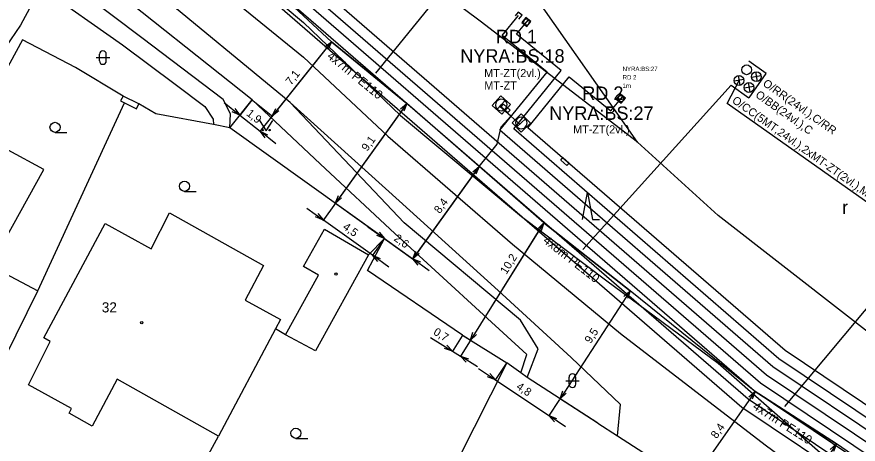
# Model space of a CAD drawing. Extents: x -836739 to -834468, y -1071001 to -1070126.
# Drawn here: x -836501 to -836438.6, y -1070362.4 to -1070330.7 of the extents above; entities that cross this region are included whole.
import ezdxf

# ---------------------------------------------------------------- set-up
doc = ezdxf.new("R2010")
doc.units = 0
for name, color, linetype in [('f001_pol_linie', 7, 'Continuous'), ('f001_pol_texty', 7, 'Continuous'), ('f001_pol_znacky', 7, 'Continuous'), ('f002_inz_linie_mimo_CETIN', 7, 'Continuous'), ('f003_opt_sit_texty', 7, 'Continuous'), ('f003_opt_sit_znacky', 7, 'Continuous'), ('f006_osa_trasy', 7, 'Continuous'), ('f006_stp_koty', 7, 'Continuous'), ('f006_stp_linie', 7, 'Continuous'), ('f006_stp_texty', 7, 'Continuous'), ('f007_rezkynet_linie', 7, 'Continuous'), ('f007_rezkynet_texty', 7, 'Continuous'), ('f007_rezkynet_znacky', 7, 'Continuous'), ('f309_rozvadec_opt', 7, 'Continuous'), ('f309_rozvadec_opt_ann', 7, 'Continuous'), ('f309_trub_konc_zar', 7, 'Continuous'), ('f309_trubicka', 7, 'Continuous'), ('f309_trubka', 7, 'Continuous')]:
    doc.layers.add(name, color=color, linetype=linetype)

msp = doc.modelspace()

# ---------------------------------------------------------------- linework, layer by layer
at = {"layer": 'f001_pol_linie'}
for points in [[(-836356.62, -1070406.87), (-836370.19, -1070399.44), (-836385.43, -1070392.2), (-836396.38, -1070386.03), (-836404.41, -1070381.11), (-836409.87, -1070376.61), (-836425.28, -1070363.93), (-836449.03, -1070345.44), (-836455, -1070340), (-836462.64, -1070329.11), (-836464.81, -1070325.47), (-836465.74, -1070321.03), (-836464.89, -1070314.87), (-836461.62, -1070306.74), (-836456.41, -1070297.54), (-836450.95, -1070288.2), (-836447.03, -1070272.79), (-836441.38, -1070260.76)], [(-836496.52, -1070319.54), (-836488.05, -1070326.94), (-836479.74, -1070333.71), (-836473.51, -1070339.57), (-836464.27, -1070347.56), (-836456.25, -1070354.2), (-836445.54, -1070362.45), (-836432.86, -1070371.82), (-836421.65, -1070379.55), (-836415.3, -1070382.95)], [(-836490.91, -1070321.78), (-836479.74, -1070331.15), (-836472.55, -1070338.03), (-836463.6, -1070345.51), (-836457.27, -1070350.28), (-836449.01, -1070356.39), (-836440.87, -1070363.54), (-836429.17, -1070372.36), (-836419.16, -1070378.17), (-836410.31, -1070384.67), (-836403.72, -1070387.61), (-836401.28, -1070388.23), (-836398.49, -1070390.5), (-836396.2, -1070392.51)], [(-836456.49, -1070361.78), (-836456.25, -1070359.46), (-836459.92, -1070355.96), (-836465.33, -1070351.01), (-836472.65, -1070344.35), (-836480.74, -1070337.07), (-836490.99, -1070328.59), (-836496.17, -1070324.43), (-836496.72, -1070324.41), (-836497.13, -1070324.67), (-836498.53, -1070327.13), (-836499.22, -1070328.53), (-836500.71, -1070331.34), (-836502.21, -1070333.5), (-836505.09, -1070337.45), (-836506.09, -1070338.88), (-836509.04, -1070344.01), (-836513.54, -1070341.59), (-836515.98, -1070341.87)], [(-836455, -1070340), (-836466.66, -1070331.05), (-836473.91, -1070325.6), (-836480.18, -1070324.33)], [(-836485.21, -1070338.94), (-836485.15, -1070337.91), (-836485.7, -1070336.85), (-836491.73, -1070332.27), (-836498.53, -1070327.13)], [(-836485.21, -1070338.94), (-836483.56, -1070336.88), (-836494.94, -1070327.8)], [(-836499.22, -1070328.53), (-836493.15, -1070332.79), (-836489.26, -1070335.71), (-836487.05, -1070337.37), (-836486.43, -1070338.3), (-836486.41, -1070338.71)], [(-836493.1, -1070336.59), (-836496.65, -1070334.47), (-836500.57, -1070332.42), (-836503.41, -1070337.61)], [(-836491.94, -1070337.17), (-836493.1, -1070336.59), (-836493.3, -1070336.95), (-836493.01, -1070337.1), (-836492.13, -1070337.55), (-836491.94, -1070337.17)], [(-836502.34, -1070355.64), (-836501.82, -1070355.9), (-836499.44, -1070351.03), (-836494.05, -1070339.35), (-836493.01, -1070337.1)], [(-836490.7, -1070337.9), (-836491.94, -1070337.17)], [(-836463.65, -1070357.11), (-836463.2, -1070355.75), (-836466.41, -1070352.81), (-836472.98, -1070346.78), (-836478.5, -1070341.63), (-836483.56, -1070336.88)], [(-836463.18, -1070357.45), (-836462.35, -1070355.33), (-836463.68, -1070353.2), (-836472.3, -1070346), (-836480.74, -1070337.07)], [(-836485.21, -1070338.94), (-836486.41, -1070338.71), (-836490.7, -1070337.9)], [(-836502.49, -1070348.34), (-836498.99, -1070342.03), (-836504.3, -1070339.18)], [(-836467.97, -1070354.32), (-836475.01, -1070349.53), (-836473.75, -1070347.16), (-836485.21, -1070338.94)], [(-836486.05, -1070361.8), (-836493.56, -1070357.58), (-836495.41, -1070361.07), (-836497.11, -1070360.09), (-836496.94, -1070359.76), (-836500.13, -1070357.99), (-836498.52, -1070354.78), (-836498.99, -1070354.52), (-836494.45, -1070346.05), (-836491.04, -1070347.91), (-836489.68, -1070345.25), (-836482.72, -1070349.16), (-836484.08, -1070351.72), (-836481.46, -1070353.16), (-836481.83, -1070353.85), (-836486.05, -1070361.8)], [(-836508.36, -1070346.32), (-836499.44, -1070351.03)], [(-836478.19, -1070346.45), (-836474.93, -1070348.36), (-836478.86, -1070355.48), (-836481.08, -1070354.28), (-836478.63, -1070349.88), (-836479.76, -1070349.22), (-836478.19, -1070346.45)], [(-836474.93, -1070348.36), (-836473.75, -1070347.16)], [(-836481.08, -1070354.28), (-836481.83, -1070353.85)], [(-836467.97, -1070354.32), (-836464.69, -1070356.37)], [(-836467.97, -1070354.32), (-836464.69, -1070356.37)], [(-836464.69, -1070356.37), (-836475.54, -1070377.9)], [(-836457.94, -1070360.84), (-836463.18, -1070357.45), (-836463.65, -1070357.11), (-836464.69, -1070356.37)], [(-836457.94, -1070360.84), (-836456.49, -1070361.78)], [(-836457.94, -1070360.84), (-836456.49, -1070361.78)], [(-836490.64, -1070370.23), (-836486.05, -1070361.8)], [(-836456.49, -1070361.78), (-836452.99, -1070364.02)]]:
    msp.add_lwpolyline(points, dxfattribs=at)
at = {"layer": 'f001_pol_znacky'}
for p, q in [((-836494.86, -1070333.99), (-836494.86, -1070333.49)), ((-836494.36, -1070333.99), (-836494.36, -1070333.49)), ((-836495.11, -1070333.74), (-836494.11, -1070333.74)), ((-836498.16, -1070339.285), (-836497.285, -1070339.285)), ((-836488.57, -1070343.655), (-836487.695, -1070343.655)), ((-836460.32, -1070357.69), (-836459.32, -1070357.69)), ((-836460.07, -1070357.94), (-836460.07, -1070357.44)), ((-836459.57, -1070357.94), (-836459.57, -1070357.44)), ((-836480.31, -1070361.965), (-836479.435, -1070361.965))]:
    msp.add_line(p, q, dxfattribs=at)
for points in [[(-836483.01, -1070338.41), (-836482.51, -1070339.16), (-836482.01, -1070338.41)], [(-836459.075, -1070345.75), (-836458.7, -1070343.75), (-836458.325, -1070345.75), (-836457.825, -1070345.75)]]:
    msp.add_lwpolyline(points, dxfattribs=at)
for centre, radius in [((-836498.16, -1070338.91), 0.375), ((-836482.76, -1070339.11), 0.05), ((-836482.26, -1070339.11), 0.05), ((-836488.57, -1070343.28), 0.375), ((-836477.34, -1070349.79), 0.0875), ((-836491.73, -1070353.4), 0.0875), ((-836480.31, -1070361.59), 0.375)]:
    msp.add_circle(centre, radius, dxfattribs=at)
for centre, start, end in [((-836494.61, -1070333.49), 0, 179.99999), ((-836494.61, -1070333.99), 179.99999, 359.99999), ((-836459.82, -1070357.44), 0, 179.99999), ((-836459.82, -1070357.94), 179.99999, 359.99999)]:
    msp.add_arc(centre, 0.25, start, end, dxfattribs=at)
at = {"layer": 'f002_inz_linie_mimo_CETIN'}
for points in [[(-836465.09, -1070337.39), (-836464.93, -1070337.2), (-836464.44, -1070337.63), (-836464.61, -1070337.82)], [(-836465.09, -1070337.39), (-836464.93, -1070337.2), (-836464.44, -1070337.63), (-836464.61, -1070337.82)], [(-836465.09, -1070337.39), (-836464.61, -1070337.82)], [(-836465.09, -1070337.39), (-836464.61, -1070337.82)], [(-836460.69, -1070341.34), (-836460.53, -1070341.15), (-836460.07, -1070341.56), (-836460.23, -1070341.75)], [(-836460.69, -1070341.34), (-836460.53, -1070341.15), (-836460.07, -1070341.56), (-836460.23, -1070341.75)], [(-836460.69, -1070341.34), (-836460.23, -1070341.75)], [(-836460.69, -1070341.34), (-836460.23, -1070341.75)]]:
    msp.add_lwpolyline(points, dxfattribs=at)
at = {"layer": 'f003_opt_sit_znacky'}
for p, q in [((-836464.81, -1070336.929), (-836465.39, -1070337.571)), ((-836464.811, -1070336.93), (-836464.81, -1070336.929)), ((-836463.31, -1070338.28), (-836463.93, -1070338.88)), ((-836463.31, -1070338.28), (-836463.31, -1070338.28))]:
    msp.add_line(p, q, dxfattribs=at)
for points in [[(-836465.776, -1070337.286), (-836465.064, -1070337.93), (-836464.42, -1070337.217), (-836465.133, -1070336.574)], [(-836464.297, -1070338.571), (-836463.629, -1070339.261), (-836462.94, -1070338.593), (-836463.607, -1070337.903)]]:
    msp.add_lwpolyline(points, close=True, dxfattribs=at)
for centre, start, end in [((-836465.098, -1070337.252), 48.27463, 227.54704), ((-836465.098, -1070337.252), 227.50629, 48.31453), ((-836463.618, -1070338.582), 44.42461, 223.69701), ((-836463.618, -1070338.583), 223.65626, 44.4645)]:
    msp.add_arc(centre, 0.432, start, end, dxfattribs=at)
at = {"layer": 'f006_osa_trasy'}
for points in [[(-836466.74, -1070341.81), (-836472.08, -1070337.14), (-836477.67, -1070332.56), (-836497.8, -1070313.84), (-836500.26, -1070310.81)], [(-836464.39, -1070338.07), (-836465.2, -1070337.36), (-836465.1, -1070337.25)], [(-836466.74, -1070341.81), (-836465.39, -1070340.15), (-836465.1, -1070338.88), (-836464.39, -1070338.07)], [(-836464.39, -1070338.07), (-836463.73, -1070338.68), (-836463.62, -1070338.58)], [(-836435.11, -1070365.91), (-836440.26, -1070362.37), (-836446.35, -1070358.45), (-836455.55, -1070351.02), (-836461.95, -1070346), (-836466.74, -1070341.81)]]:
    msp.add_lwpolyline(points, dxfattribs=at)
at = {"layer": 'f006_stp_koty'}
for p, q in [((-836477.707, -1070332.607), (-836483.006, -1070339.247)), ((-836477.67, -1070332.56), (-836482.067, -1070338.071)), ((-836485.634, -1070337.074), (-836484.461, -1070338.009)), ((-836483.597, -1070336.927), (-836484.499, -1070338.056)), ((-836483.513, -1070336.917), (-836482.02, -1070338.108)), ((-836472.115, -1070337.189), (-836478.312, -1070345.829)), ((-836472.08, -1070337.14), (-836477.393, -1070344.547)), ((-836484.461, -1070338.009), (-836482.968, -1070339.2)), ((-836481.796, -1070340.136), (-836482.968, -1070339.2)), ((-836466.775, -1070341.859), (-836471.69, -1070348.711)), ((-836466.74, -1070341.81), (-836471.655, -1070348.663)), ((-836473.799, -1070347.125), (-836477.442, -1070344.512)), ((-836479.496, -1070344.906), (-836478.277, -1070345.78)), ((-836474.634, -1070348.393), (-836478.277, -1070345.78)), ((-836461.982, -1070346.051), (-836468.149, -1070355.919)), ((-836461.95, -1070346), (-836467.38, -1070354.689)), ((-836474.969, -1070346.286), (-836473.75, -1070347.16)), ((-836473.785, -1070347.209), (-836474.669, -1070348.442)), ((-836473.75, -1070347.16), (-836471.655, -1070348.663)), ((-836473.701, -1070347.195), (-836471.606, -1070348.698)), ((-836473.415, -1070349.267), (-836474.634, -1070348.393)), ((-836470.436, -1070349.537), (-836471.655, -1070348.663)), ((-836455.55, -1070351.02), (-836460.734, -1070359.033)), ((-836470.336, -1070354.481), (-836468.707, -1070355.499)), ((-836468.002, -1070354.371), (-836468.739, -1070355.55)), ((-836467.919, -1070354.352), (-836467.329, -1070354.72)), ((-836468.707, -1070355.499), (-836468.117, -1070355.868)), ((-836466.845, -1070356.663), (-836468.117, -1070355.868)), ((-836464.724, -1070356.42), (-836465.562, -1070357.665)), ((-836466.773, -1070356.778), (-836465.529, -1070357.616)), ((-836465.529, -1070357.616), (-836461.573, -1070360.279)), ((-836446.29, -1070358.492), (-836451.09, -1070365.35)), ((-836446.301, -1070358.484), (-836446.24, -1070358.527)), ((-836460.768, -1070359.083), (-836461.606, -1070360.328)), ((-836457.99, -1070360.807), (-836460.784, -1070359)), ((-836460.328, -1070361.116), (-836461.573, -1070360.279)), ((-836440.26, -1070362.37), (-836445.015, -1070369.413))]:
    msp.add_line(p, q, dxfattribs=at)
for points in [[(-836478.161, -1070332.935), (-836477.67, -1070332.56), (-836477.927, -1070333.123)], [(-836472.552, -1070337.54), (-836472.08, -1070337.14), (-836472.308, -1070337.715)], [(-836484.837, -1070337.518), (-836484.461, -1070338.009), (-836485.024, -1070337.752)], [(-836481.576, -1070337.696), (-836482.067, -1070338.071), (-836481.81, -1070337.509)], [(-836482.593, -1070339.692), (-836482.968, -1070339.2), (-836482.406, -1070339.457)], [(-836467.212, -1070342.21), (-836466.74, -1070341.81), (-836466.968, -1070342.385)], [(-836476.921, -1070344.147), (-836477.393, -1070344.547), (-836477.165, -1070343.972)], [(-836478.677, -1070345.308), (-836478.277, -1070345.78), (-836478.852, -1070345.552)], [(-836462.395, -1070346.429), (-836461.95, -1070346), (-836462.141, -1070346.588)], [(-836474.15, -1070346.688), (-836473.75, -1070347.16), (-836474.325, -1070346.932)], [(-836474.234, -1070348.864), (-836474.634, -1070348.393), (-836474.059, -1070348.621)], [(-836471.184, -1070348.262), (-836471.655, -1070348.663), (-836471.427, -1070348.088)], [(-836471.255, -1070349.134), (-836471.655, -1070348.663), (-836471.08, -1070348.89)], [(-836456.002, -1070351.442), (-836455.55, -1070351.02), (-836455.75, -1070351.605)], [(-836466.935, -1070354.259), (-836467.38, -1070354.689), (-836467.19, -1070354.1)], [(-836469.136, -1070355.054), (-836468.707, -1070355.499), (-836469.295, -1070355.309)], [(-836467.688, -1070356.313), (-836468.117, -1070355.868), (-836467.529, -1070356.059)], [(-836465.943, -1070357.156), (-836465.529, -1070357.616), (-836466.11, -1070357.405)], [(-836460.282, -1070358.61), (-836460.734, -1070359.033), (-836460.534, -1070358.447)], [(-836446.757, -1070358.898), (-836446.29, -1070358.492), (-836446.511, -1070359.07)], [(-836461.159, -1070360.738), (-836461.573, -1070360.279), (-836460.991, -1070360.489)], [(-836440.72, -1070362.783), (-836440.26, -1070362.37), (-836440.471, -1070362.951)]]:
    msp.add_lwpolyline(points, dxfattribs=at)
at = {"layer": 'f006_stp_linie'}
for points in [[(-836477.67, -1070332.56), (-836472.08, -1070337.14)], [(-836461.95, -1070346), (-836455.55, -1070351.02)], [(-836446.35, -1070358.45), (-836440.26, -1070362.37)]]:
    msp.add_lwpolyline(points, dxfattribs=at)
at = {"layer": 'f007_rezkynet_linie'}
for points in [[(-836464.18, -1070322.29), (-836474.417, -1070334.902)], [(-836434.23, -1070347.12), (-836448.346, -1070337.14), (-836447.473, -1070335.438)], [(-836448.05, -1070335.78), (-836459.042, -1070347.963)], [(-836435.31, -1070349.07), (-836444.113, -1070359.593)]]:
    msp.add_lwpolyline(points, dxfattribs=at)
at = {"layer": 'f007_rezkynet_znacky'}
for p, q in [((-836445.454, -1070334.918), (-836446.76, -1070333.994)), ((-836446.248, -1070334.801), (-836446.125, -1070335.516)), ((-836447.115, -1070335.376), (-836447.831, -1070335.499)), ((-836447.535, -1070335.08), (-836447.411, -1070335.795)), ((-836446.727, -1070336.72), (-836445.454, -1070334.918)), ((-836445.829, -1070335.097), (-836446.545, -1070335.22)), ((-836448.047, -1070335.787), (-836446.741, -1070336.711)), ((-836446.381, -1070335.895), (-836447.096, -1070336.018)), ((-836446.8, -1070335.599), (-836446.676, -1070336.314))]:
    msp.add_line(p, q, dxfattribs=at)
for centre in [(-836446.914, -1070334.645), (-836446.187, -1070335.159), (-836447.473, -1070335.438), (-836446.739, -1070335.957)]:
    msp.add_circle(centre, 0.363, dxfattribs=at)
at = {"layer": 'f309_rozvadec_opt'}
for p, q in [((-836463.093, -1070330.934), (-836463.365, -1070331.27)), ((-836463.093, -1070330.935), (-836463.093, -1070330.934)), ((-836456.101, -1070336.619), (-836456.373, -1070336.954)), ((-836456.101, -1070336.619), (-836456.101, -1070336.619))]:
    msp.add_line(p, q, dxfattribs=at)
for points in [[(-836463.566, -1070331.138), (-836463.193, -1070331.44), (-836462.891, -1070331.068), (-836463.263, -1070330.765)], [(-836456.574, -1070336.822), (-836456.201, -1070337.124), (-836455.899, -1070336.752), (-836456.271, -1070336.449)]]:
    msp.add_lwpolyline(points, close=True, dxfattribs=at)
for centre, start, end in [((-836463.228, -1070331.103), 51.29622, 230.56863), ((-836463.228, -1070331.103), 230.52788, 51.33612), ((-836456.236, -1070336.787), 51.26516, 230.53756), ((-836456.236, -1070336.787), 230.49681, 51.30505)]:
    msp.add_arc(centre, 0.216, start, end, dxfattribs=at)
at = {"layer": 'f309_trub_konc_zar'}
msp.add_lwpolyline([(-836463.783, -1070330.894), (-836463.546, -1070330.603), (-836463.837, -1070330.366), (-836464.074, -1070330.657)], dxfattribs=at)
at = {"layer": 'f309_trubicka'}
for points in [[(-836402.147, -1070370.441), (-836402.99, -1070373.112), (-836405.43, -1070380.833), (-836407.034, -1070380.23), (-836427.739, -1070368.239), (-836444.982, -1070356.659), (-836465.205, -1070339.123), (-836461.7, -1070334.81), (-836465.016, -1070332.115), (-836463.81, -1070330.63)], [(-836400.273, -1070369.489), (-836402.644, -1070369.527), (-836403.705, -1070372.886), (-836405.907, -1070379.853), (-836406.712, -1070379.55), (-836427.342, -1070367.602), (-836444.526, -1070356.062), (-836464.165, -1070339.032), (-836460.645, -1070334.701), (-836463.961, -1070332.006), (-836463.228, -1070331.103)], [(-836400.273, -1070369.489), (-836403.36, -1070369.301), (-836404.42, -1070372.66), (-836406.384, -1070378.872), (-836406.39, -1070378.87), (-836426.945, -1070366.965), (-836444.07, -1070355.465), (-836463.125, -1070338.941), (-836460.063, -1070335.174), (-836456.969, -1070337.689), (-836456.236, -1070336.787)]]:
    msp.add_lwpolyline(points, dxfattribs=at)
at = {"layer": 'f309_trubka'}
for points in [[(-836257.543, -1070422.322), (-836258.258, -1070422.096), (-836259.283, -1070421.772), (-836260.99, -1070422.47), (-836266.6, -1070439.21), (-836271.52, -1070438.59), (-836350.1, -1070406.54), (-836380.46, -1070395.41), (-836397.84, -1070386.09), (-836408, -1070382.27), (-836428.93, -1070370.15), (-836446.35, -1070358.45), (-836497.8, -1070313.84), (-836500.259, -1070310.812)], [(-836499.139, -1070311.001), (-836497.259, -1070313.316), (-836445.894, -1070357.853), (-836428.533, -1070369.513), (-836407.678, -1070381.59), (-836397.529, -1070385.406), (-836380.152, -1070394.724), (-836349.829, -1070405.84), (-836271.328, -1070437.858), (-836267.116, -1070438.389), (-836261.592, -1070421.906), (-836259.316, -1070420.975), (-836258.032, -1070421.38), (-836257.317, -1070421.606)], [(-836500.901, -1070311.21), (-836500.428, -1070311.792), (-836498.049, -1070311.154), (-836496.718, -1070312.792), (-836445.438, -1070357.256), (-836428.136, -1070368.876), (-836407.356, -1070380.91), (-836404.953, -1070381.813), (-836402.275, -1070373.338)], [(-836501.069, -1070312.194), (-836498.882, -1070314.888), (-836447.262, -1070359.644), (-836429.724, -1070371.424), (-836408.644, -1070383.63), (-836398.462, -1070387.458), (-836381.076, -1070396.782), (-836350.642, -1070407.94), (-836271.904, -1070440.054), (-836265.568, -1070440.852), (-836259.786, -1070423.598), (-836259.218, -1070423.366), (-836257.995, -1070423.753)], [(-836499.902, -1070312.441), (-836498.341, -1070314.364), (-836446.806, -1070359.047), (-836429.327, -1070370.787), (-836408.322, -1070382.95), (-836398.151, -1070386.774), (-836380.768, -1070396.096), (-836350.371, -1070407.24), (-836271.712, -1070439.322), (-836266.084, -1070440.031), (-836260.388, -1070423.034), (-836259.25, -1070422.569), (-836257.769, -1070423.038)]]:
    msp.add_lwpolyline(points, dxfattribs=at)

# ---------------------------------------------------------------- texts
at = {"layer": 'f001_pol_texty'}
msp.add_text('32', height=0.75, dxfattribs=at).set_placement((-836494.69, -1070352.63))
at = {"layer": 'f001_pol_znacky'}
msp.add_text('r', height=1, dxfattribs=at).set_placement((-836439.838, -1070345.342))
at = {"layer": 'f003_opt_sit_texty'}
for s, height, p in [('RD 1', 1, (-836465.49, -1070332.68)), ('NYRA:BS:18', 1, (-836468.13, -1070334.12)), ('MT-ZT(2vl.)', 0.6, (-836466.36, -1070335.19)), ('MT-ZT', 0.6, (-836466.35, -1070336.11)), ('RD 2', 1, (-836459.09, -1070336.88)), ('NYRA:BS:27', 1, (-836461.54, -1070338.36)), ('MT-ZT(2vl.)', 0.6, (-836459.77, -1070339.36))]:
    msp.add_text(s, height=height, dxfattribs=at).set_placement(p)
at = {"layer": 'f006_stp_koty'}
for s, rotation, p in [('7,1', 51.41395, (-836480.665, -1070335.832)), ('1,9', 321.41395, (-836484.026, -1070337.973)), ('9,1', 54.34898, (-836475.022, -1070340.726)), ('8,4', 54.34898, (-836469.647, -1070345.348)), ('4,5', 324.34898, (-836476.887, -1070346.407)), ('2,6', 324.34898, (-836473.104, -1070347.254)), ('10,2', 57.99462, (-836464.711, -1070349.851)), ('0,7', 327.99462, (-836470.177, -1070354.227)), ('9,5', 57.09929, (-836458.469, -1070354.98)), ('4,8', 326.05335, (-836464.036, -1070358.259)), ('8,4', 55.00798, (-836449.135, -1070362.034))]:
    msp.add_text(s, height=0.6, rotation=rotation, dxfattribs=at).set_placement(p)
at = {"layer": 'f006_stp_texty'}
for s, rotation, p in [('4x7m PE110', 320.67154, (-836478.057, -1070333.725)), ('4x8m PE110', 321.89025, (-836462.046, -1070347.405)), ('4x7m PE110', 327.2315, (-836446.513, -1070359.749))]:
    msp.add_text(s, height=0.65, rotation=rotation, dxfattribs=at).set_placement(p)
at = {"layer": 'f007_rezkynet_texty'}
for s, p in [('O/RR(24vl.),C/RR', (-836445.765, -1070335.777)), ('O/CC(5MT,24vl.),2xMT-ZT(2vl.),MT-ZT', (-836448.046, -1070337.038)), ('O/BB(24vl.),C', (-836446.315, -1070336.622))]:
    msp.add_text(s, height=0.6, rotation=324.74503, dxfattribs=at).set_placement(p)
at = {"layer": 'f309_rozvadec_opt_ann'}
for s, p in [('NYRA:BS:27', (-836456.1, -1070334.738)), ('RD 2', (-836456.1, -1070335.363)), ('1m', (-836456.1, -1070335.988))]:
    msp.add_text(s, height=0.325, dxfattribs=at).set_placement(p)

doc.saveas('drawing.dxf')
